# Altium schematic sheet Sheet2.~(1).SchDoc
size A
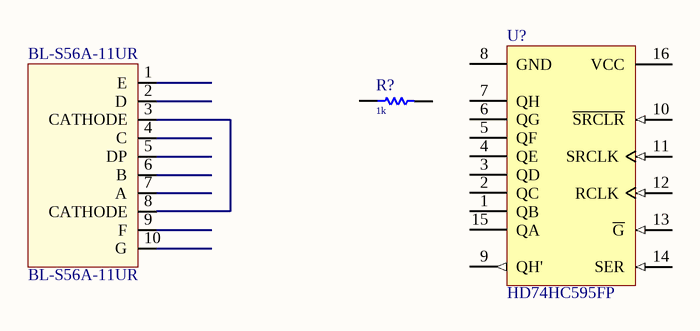
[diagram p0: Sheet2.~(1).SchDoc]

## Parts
BL-S56A-11UR  BL-S56A-11UR  [BL-S56A-11UR]
R?  1k  [RES 0805N (2012)]
U?  HD74HC595FP  [PRSP0016DH-B_N]

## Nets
NetBL-S56A-11UR_3: BL-S56A-11UR.3(CATHODE) BL-S56A-11UR.8(CATHODE)

Not connected (* = marked no-connect by the designer): BL-S56A-11UR 1(E) 2(D) 4(C) 5(DP) 6(B) 7(A) 9(F) 10(G); R? 1 2; U? 1(QB) 2(QC) 3(QD) 4(QE) 5(QF) 6(QG) 7(QH) 8(GND) 9(QH') 10(~{SRCLR}) 11(SRCLK) 12(RCLK) 13(~{G}) 14(SER) 15(QA) 16(VCC)

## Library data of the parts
BL-S56A-11UR = Component_1
R? = Res1: Resistor
U? = HD74HC595FP: 8-bit Shift Register / Latch with 3-State Outputs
